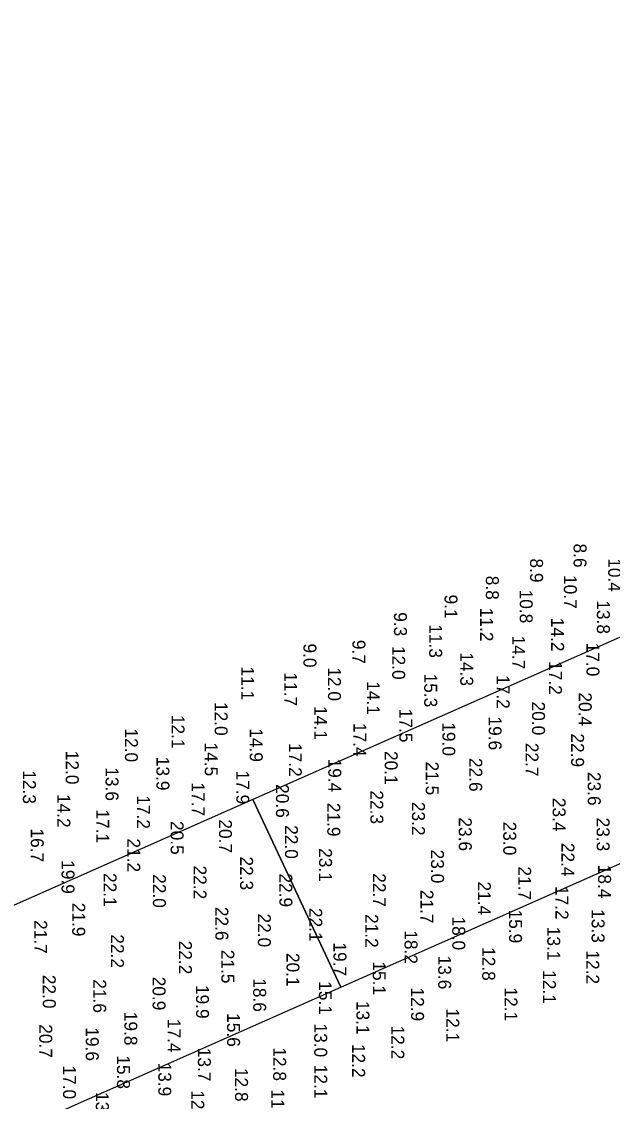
# Model space of a CAD drawing. Extents: x 1178573 to 1187098, y 693282 to 751751.
# Drawn here: x 1183506 to 1184076, y 725383 to 726426 of the extents above; entities that cross this region are included whole.
import ezdxf

# ---------------------------------------------------------------- set-up
doc = ezdxf.new("R2010")
doc.units = 0
for name, color, linetype in [('G-ANNO-PATT', 7, 'Continuous'), ('V-HYDS-SOUN', 7, 'Continuous'), ('V-HYDS-SOUN-EXSS', 7, 'Continuous')]:
    doc.layers.add(name, color=color, linetype=linetype)

msp = doc.modelspace()

# ---------------------------------------------------------------- linework, layer by layer
at = {"layer": 'G-ANNO-PATT'}
for p, q in [((1185426.4, 726425.6), (1183729.3, 725674.5)), ((1183814.1, 725493.3), (1183729.3, 725674.5)), ((1183729.3, 725674.5), (1183814.1, 725493.3)), ((1183814.1, 725493.3), (1184193, 725661))]:
    msp.add_line(p, q, dxfattribs=at)
for points in [[(1183729.3, 725674.5), (1182702.6, 725220.1), (1182458.9, 724847.4), (1182432.2, 724780.3)], [(1182405, 724104.2), (1182613, 724626.3), (1182838, 724970.3), (1183134, 725192.3), (1183814.1, 725493.3)]]:
    msp.add_lwpolyline(points, dxfattribs=at)

# ---------------------------------------------------------------- texts
at = {"layer": 'V-HYDS-SOUN'}
for s, p in [('8.6', (1184038.8, 725921.7)), ('8.9', (1183996.8, 725907.3)), ('10.4 ', (1184072.2, 725907.5)), ('8.8', (1183954.1, 725890.6)), ('10.7 ', (1184029.4, 725891.3)), ('9.1', (1183914.2, 725872.4)), ('13.8 ', (1184061.3, 725866.9)), ('9.3', (1183865.4, 725855.4)), ('11.2 ', (1183948.6, 725859.7)), ('11.3 ', (1183899.4, 725843.8)), ('14.2 ', (1184017.1, 725850)), ('14.7 ', (1183979.5, 725832.8)), ('9.0', (1183778, 725825.2)), ('9.7', (1183825.3, 725828.7)), ('12.0 ', (1183863.7, 725822.8)), ('17.0 ', (1184051.2, 725826)), ('14.3 ', (1183929.4, 725816.7)), ('11.1 ', (1183717.9, 725803)), ('12.0 ', (1183801.7, 725802.2)), ('11.7 ', (1183759.4, 725797.3)), ('15.3 ', (1183894.6, 725796.1)), ('17.2 ', (1183964.6, 725794.7)), ('14.1 ', (1183839.2, 725788.8)), ('20.0 ', (1183998.7, 725769.1)), ('20.4 ', (1184043.8, 725778)), ('12.0 ', (1183692.3, 725768.7)), ('14.1 ', (1183788.4, 725764.7)), ('17.5 ', (1183870.6, 725762.2)), ('12.1 ', (1183650.7, 725756.3)), ('19.0 ', (1183912.1, 725749.1)), ('19.6 ', (1183956.8, 725754.7)), ('12.0 ', (1183605.7, 725743.2)), ('14.9 ', (1183726.2, 725743.4)), ('17.4 ', (1183826.3, 725748.5)), ('14.5 ', (1183682.7, 725729.6)), ('17.2 ', (1183763.9, 725729.1)), ('22.7 ', (1183992.4, 725729.3)), ('12.0 ', (1183548.6, 725721.6)), ('20.1 ', (1183856.5, 725721.4)), ('13.9 ', (1183636.1, 725715.8)), ('19.4 ', (1183802, 725714.1)), ('21.5 ', (1183896.1, 725711.2)), ('22.6 ', (1183938.1, 725714.7)), ('12.3 ', (1183507.2, 725702.8)), ('13.6 ', (1183587, 725705.7)), ('17.9 ', (1183713.2, 725702.5)), ('17.7 ', (1183670.1, 725691.1)), ('20.6 ', (1183751.5, 725689.4)), ('14.2 ', (1183540.5, 725679.9)), ('17.2 ', (1183617.3, 725678.7)), ('22.3 ', (1183842.6, 725683.4)), ('23.4 ', (1184018.6, 725676.2)), ('21.9 ', (1183801, 725671.4)), ('23.2 ', (1183882.8, 725672.3)), ('17.1 ', (1183578, 725665)), ('20.7 ', (1183696.5, 725655.4)), ('23.6 ', (1183928, 725657.3)), ('23.3 ', (1184061.1, 725657.1)), ('16.7 ', (1183514.8, 725646.6)), ('20.5 ', (1183649.8, 725653.8)), ('22.0 ', (1183760.2, 725649.8)), ('23.0 ', (1183970.9, 725653.2)), ('21.2 ', (1183608, 725637)), ('23.1 ', (1183793.1, 725627.6)), ('23.0 ', (1183901.2, 725626.2)), ('22.4 ', (1184027.1, 725632.7)), ('19.9 ', (1183544.5, 725616)), ('22.3 ', (1183716.9, 725619.6)), ('22.1 ', (1183585.1, 725603.6)), ('22.0 ', (1183632.7, 725602.5)), ('22.2 ', (1183671.9, 725610.8)), ('22.9 ', (1183754.8, 725603.2)), ('22.7 ', (1183845, 725603.4)), ('21.7 ', (1183985.3, 725610)), ('18.4 ', (1184062.5, 725611.6)), ('21.4 ', (1183946.4, 725595.4)), ('21.7 ', (1183891, 725587.4)), ('17.2 ', (1184021.3, 725591.1)), ('21.9 ', (1183554.8, 725574.9)), ('22.6 ', (1183693, 725570.9)), ('22.0 ', (1183734, 725564.5)), ('22.1 ', (1183783.6, 725569.9)), ('21.2 ', (1183837.7, 725564)), ('18.0 ', (1183921.7, 725561.6)), ('15.9 ', (1183976.5, 725568.3)), ('13.3 ', (1184056.2, 725568.7)), ('21.7 ', (1183518.1, 725558.2)), ('13.1 ', (1184013.4, 725551.7)), ('22.2 ', (1183592.2, 725544.4)), ('18.2 ', (1183875.6, 725548.3)), ('22.2 ', (1183657.8, 725538.3)), ('21.5 ', (1183698.8, 725529.5)), ('19.7 ', (1183807, 725536.6)), ('12.8 ', (1183950.6, 725532.1)), ('20.1 ', (1183761.6, 725526.4)), ('13.6 ', (1183908.1, 725523.8)), ('12.2 ', (1184051.1, 725528.9)), ('15.1 ', (1183845, 725518.3)), ('12.1 ', (1184009.2, 725509.8)), ('22.0 ', (1183526.4, 725505.3)), ('21.6 ', (1183575.1, 725501)), ('20.9 ', (1183632.4, 725503.5)), ('18.6 ', (1183729.5, 725502)), ('15.1 ', (1183792.9, 725499.2)), ('19.9 ', (1183674.3, 725495.5)), ('12.9 ', (1183881.9, 725493.1)), ('12.1 ', (1183972.1, 725493.1)), ('13.1 ', (1183829.2, 725480.1)), ('19.8 ', (1183605.1, 725469.6)), ('15.6 ', (1183704.3, 725468.3)), ('12.1 ', (1183915.9, 725472.8)), ('20.7 ', (1183523, 725457.6)), ('17.4 ', (1183646.9, 725462.8)), ('13.0 ', (1183788.4, 725458.3)), ('19.6 ', (1183567.9, 725454.6)), ('12.2 ', (1183862.9, 725456.3)), ('12.2 ', (1183825, 725438.6)), ('15.8 ', (1183598, 725427.6)), ('13.7 ', (1183676.1, 725434.9)), ('12.8 ', (1183748.8, 725435.3)), ('17.0 ', (1183545.9, 725417.8)), ('13.9 ', (1183637.9, 725420.6)), ('12.8 ', (1183712, 725415.4)), ('12.1 ', (1183788.5, 725418.5)), ('11.9 ', (1183747, 725394.7)), ('13.8 ', (1183577.6, 725392.1)), ('12.8 ', (1183669.7, 725393.9))]:
    msp.add_text(s, height=12.5, rotation=270, dxfattribs=at).set_placement(p)
at = {"layer": 'V-HYDS-SOUN-EXSS'}
for s, p in [('10.8 ', (1183986.8, 725877.2)), ('17.2 ', (1184015.1, 725808.2)), ('22.9 ', (1184036.4, 725738.4)), ('23.6 ', (1184052.5, 725701.2))]:
    msp.add_text(s, height=12.5, rotation=270, dxfattribs=at).set_placement(p)

doc.saveas('drawing.dxf')
